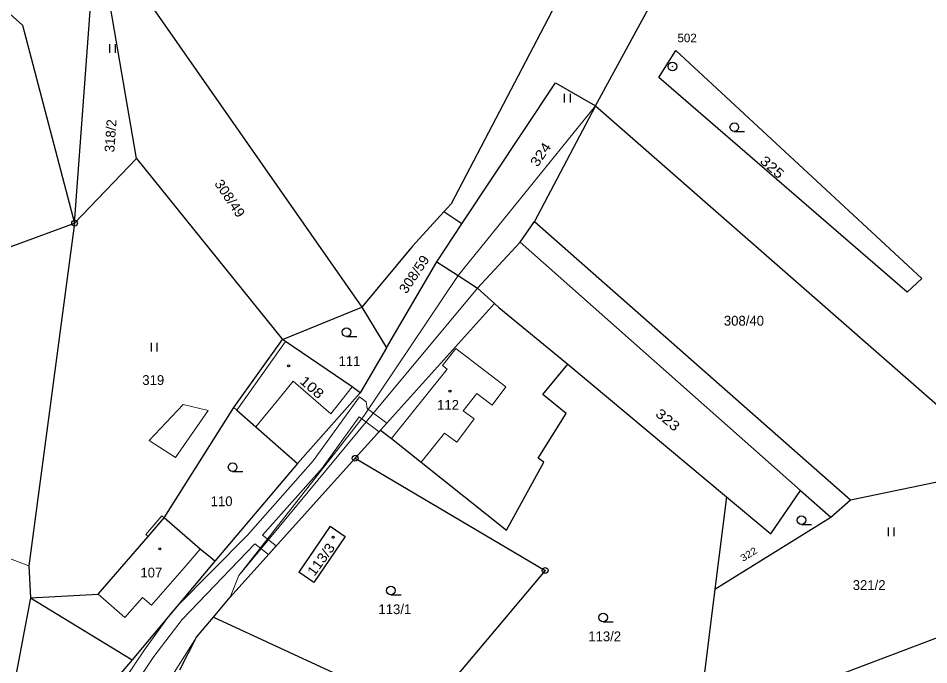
# Model space of a CAD drawing. Extents: x -504006 to -501322, y -1128098 to -1124665.
# Drawn here: x -502579.9 to -502422.2, y -1126415.1 to -1126303.1 of the extents above; entities that cross this region are included whole.
import ezdxf
from ezdxf.enums import TextEntityAlignment as Align

# ---------------------------------------------------------------- set-up
doc = ezdxf.new("R2010")
doc.units = 0
doc.header["$LTSCALE"] = 0.68
for name, color, linetype, lineweight in [('1', 7, 'Continuous', 25), ('13', 7, 'Continuous', 13), ('3', 7, 'Continuous', 25), ('4', 7, 'Continuous', 13), ('5', 7, 'Continuous', 25), ('8', 7, 'Continuous', 25)]:
    doc.layers.add(name, color=color, linetype=linetype, lineweight=lineweight)
doc.layers.add('2', color=7, linetype='Continuous')

msp = doc.modelspace()

# ---------------------------------------------------------------- linework, layer by layer
at = {"layer": '1'}
for p, q in [((-502479.92, -1126318.31), (-502455.33, -1126272.95)), ((-502479.14, -1126285.99), (-502504.93, -1126335.25)), ((-502570.14, -1126338.62), (-502566.35, -1126287.36)), ((-502566.35, -1126287.36), (-502520.38, -1126353.19)), ((-502559.39, -1126327.42), (-502566.35, -1126287.36)), ((-502595.09, -1126290.13), (-502579.17, -1126304.31)), ((-502579.17, -1126304.31), (-502570.14, -1126338.62)), ((-502468.92, -1126313.37), (-502465.98, -1126308.73)), ((-502465.98, -1126308.73), (-502423.39, -1126348.19)), ((-502425.92, -1126350.57), (-502468.92, -1126313.37)), ((-502503.06, -1126338.76), (-502486.83, -1126314.3)), ((-502486.83, -1126314.3), (-502479.92, -1126318.31)), ((-502479.92, -1126318.31), (-502490.51, -1126338.36)), ((-502479.92, -1126318.31), (-502419.28, -1126371.36)), ((-502570.14, -1126338.62), (-502559.39, -1126327.42)), ((-502559.39, -1126327.42), (-502534.14, -1126358.76)), ((-502506.21, -1126336.66), (-502504.93, -1126335.25)), ((-502506.21, -1126336.66), (-502511.61, -1126342.61)), ((-502503.06, -1126338.76), (-502506.21, -1126336.66)), ((-502595.74, -1126348), (-502570.14, -1126338.62)), ((-502570.14, -1126338.62), (-502578.06, -1126397.97)), ((-502507.41, -1126345.32), (-502503.06, -1126338.76)), ((-502492.96, -1126341.91), (-502490.51, -1126338.36)), ((-502490.51, -1126338.36), (-502435.75, -1126386.52)), ((-502500.36, -1126349.87), (-502492.96, -1126341.91)), ((-502511.61, -1126342.61), (-502520.38, -1126353.19)), ((-502516.11, -1126360.23), (-502507.41, -1126345.32)), ((-502507.41, -1126345.32), (-502503.72, -1126347.7)), ((-502503.72, -1126347.7), (-502500.36, -1126349.87)), ((-502423.39, -1126348.19), (-502425.92, -1126350.57)), ((-502500.36, -1126349.87), (-502497.4, -1126352.56)), ((-502534.14, -1126358.76), (-502520.38, -1126353.19)), ((-502520.38, -1126353.19), (-502516.11, -1126360.23)), ((-502517.13, -1126374.46), (-502497.4, -1126352.56)), ((-502497.4, -1126352.56), (-502496.69, -1126353.21)), ((-502496.69, -1126353.21), (-502484.7, -1126363.05)), ((-502542.54, -1126370.58), (-502534.14, -1126358.76)), ((-502533.61, -1126359.13), (-502534.14, -1126358.76)), ((-502522.05, -1126366.99), (-502533.61, -1126359.13)), ((-502516.11, -1126360.23), (-502520.65, -1126368)), ((-502489.03, -1126368.32), (-502484.7, -1126363.05)), ((-502484.7, -1126363.05), (-502457.2, -1126386.02)), ((-502520.65, -1126368), (-502522.05, -1126366.99)), ((-502520.65, -1126368), (-502531.53, -1126380.26)), ((-502485.01, -1126371.62), (-502489.03, -1126368.32)), ((-502554.62, -1126389.67), (-502542.54, -1126370.58)), ((-502542.54, -1126370.58), (-502542.04, -1126371.01)), ((-502542.04, -1126371.01), (-502538.73, -1126373.92)), ((-502489.82, -1126379.32), (-502485.01, -1126371.62)), ((-502538.73, -1126373.92), (-502531.53, -1126380.26)), ((-502521.54, -1126379.35), (-502517.13, -1126374.46)), ((-502517.13, -1126374.46), (-502515.28, -1126375.93)), ((-502515.28, -1126375.93), (-502510.09, -1126380.04)), ((-502488.87, -1126380.05), (-502489.82, -1126379.32)), ((-502531.53, -1126380.26), (-502545.85, -1126397.19)), ((-502510.09, -1126380.04), (-502495.32, -1126391.81)), ((-502495.32, -1126391.81), (-502488.87, -1126380.05)), ((-502435.75, -1126386.52), (-502419.38, -1126383.13)), ((-502457.2, -1126386.02), (-502459.24, -1126402.04)), ((-502457.2, -1126386.02), (-502449.53, -1126392.43)), ((-502449.53, -1126392.43), (-502444.4, -1126384.92)), ((-502444.4, -1126384.92), (-502439.16, -1126389.56)), ((-502439.16, -1126389.56), (-502435.75, -1126386.52)), ((-502557.4, -1126392.88), (-502554.62, -1126389.67)), ((-502548.38, -1126395.09), (-502554.62, -1126389.67)), ((-502459.24, -1126402.04), (-502439.16, -1126389.56)), ((-502525.88, -1126391.09), (-502531.32, -1126399.06)), ((-502525.88, -1126391.09), (-502523.28, -1126392.87)), ((-502566.08, -1126402.87), (-502557.4, -1126392.88)), ((-502523.28, -1126392.87), (-502528.72, -1126400.84)), ((-502546.6, -1126396.53), (-502548.38, -1126395.09)), ((-502545.85, -1126397.19), (-502560.18, -1126414.25)), ((-502545.85, -1126397.19), (-502546.6, -1126396.53)), ((-502578.06, -1126397.97), (-502577.79, -1126403.55)), ((-502488.63, -1126398.78), (-502517.33, -1126432.89)), ((-502528.72, -1126400.84), (-502531.32, -1126399.06)), ((-502459.24, -1126402.04), (-502462.2, -1126425.6)), ((-502577.79, -1126403.55), (-502581.3, -1126422.25)), ((-502577.79, -1126403.55), (-502566.08, -1126402.87)), ((-502577.79, -1126403.55), (-502560.18, -1126414.25)), ((-502546.11, -1126406.89), (-502543.22, -1126403.41)), ((-502446.8, -1126420.25), (-502404.96, -1126404.48)), ((-502549, -1126410.36), (-502546.11, -1126406.89)), ((-502546.11, -1126406.89), (-502523.76, -1126417.19)), ((-502551.92, -1126415.99), (-502549, -1126410.36)), ((-502560.18, -1126414.25), (-502562.43, -1126416.93))]:
    msp.add_line(p, q, dxfattribs=at)
msp.add_lwpolyline([(-502543.22, -1126403.41), (-502521.54, -1126379.35), (-502488.63, -1126398.78)], dxfattribs=at)
at = {"layer": '13'}
msp.add_lwpolyline([(-502561.33, -1126421.06), (-502556.4, -1126413.68), (-502551.52, -1126407.26), (-502538.92, -1126394.17), (-502536.57, -1126396.03), (-502535.23, -1126394.54), (-502537.58, -1126392.68), (-502527.24, -1126381.06), (-502520.84, -1126372.18), (-502517.4, -1126374.76), (-502517.13, -1126374.46), (-502516.06, -1126373.27), (-502519.49, -1126370.7), (-502519.66, -1126369.57), (-502520.82, -1126368.72), (-502528.8, -1126379.8), (-502540.22, -1126392.64), (-502552.42, -1126405.01), (-502553.72, -1126406.55), (-502558.02, -1126412.52), (-502563.03, -1126420)], dxfattribs=at)
at = {"layer": '3'}
for p, q in [((-502564.061, -1126309.1), (-502564.061, -1126307.6)), ((-502563.06, -1126309.1), (-502563.06, -1126307.6)), ((-502485.261, -1126317.71), (-502485.261, -1126316.21)), ((-502484.26, -1126317.71), (-502484.26, -1126316.21)), ((-502455.873, -1126322.74), (-502454.123, -1126322.74)), ((-502556.831, -1126360.83), (-502556.831, -1126359.33)), ((-502555.83, -1126360.83), (-502555.83, -1126359.33)), ((-502523.033, -1126358.28), (-502521.283, -1126358.28)), ((-502542.763, -1126381.65), (-502541.013, -1126381.65)), ((-502444.243, -1126390.82), (-502442.493, -1126390.82)), ((-502429.171, -1126392.85), (-502429.171, -1126391.35)), ((-502428.17, -1126392.85), (-502428.17, -1126391.35)), ((-502515.353, -1126403), (-502513.603, -1126403)), ((-502478.583, -1126407.69), (-502476.833, -1126407.69))]:
    msp.add_line(p, q, dxfattribs=at)
for centre in [(-502455.8729, -1126321.9898), (-502523.0329, -1126357.5298), (-502542.7629, -1126380.8998), (-502444.2429, -1126390.0698), (-502515.3529, -1126402.2498), (-502478.5829, -1126406.9398)]:
    msp.add_circle(centre, 0.75, dxfattribs=at)
at = {"layer": '4'}
for p, q in [((-502479.92, -1126318.31), (-502503.72, -1126347.7)), ((-502492.96, -1126341.91), (-502444.4, -1126384.92)), ((-502503.72, -1126347.7), (-502520.13, -1126372.09)), ((-502519.34, -1126372.71), (-502500.36, -1126349.87)), ((-502542.04, -1126371.01), (-502533.61, -1126359.13)), ((-502506.4, -1126363.29), (-502504.12, -1126360.35)), ((-502504.12, -1126360.35), (-502495.44, -1126366.97)), ((-502515.28, -1126375.93), (-502505.59, -1126363.89)), ((-502505.59, -1126363.89), (-502506.4, -1126363.29)), ((-502532.3, -1126366.01), (-502534.5, -1126368.71)), ((-502525.76, -1126371.67), (-502532.3, -1126366.01)), ((-502522.05, -1126366.99), (-502525.76, -1126371.67)), ((-502495.44, -1126366.97), (-502497.81, -1126370.13)), ((-502534.5, -1126368.71), (-502538.73, -1126373.92)), ((-502500.45, -1126368.12), (-502502.83, -1126371.12)), ((-502497.81, -1126370.13), (-502500.45, -1126368.12)), ((-502557.25, -1126376.27), (-502551.32, -1126370.01)), ((-502551.32, -1126370.01), (-502547.01, -1126371.1)), ((-502547.01, -1126371.1), (-502552.66, -1126379.23)), ((-502520.13, -1126372.09), (-502541.71, -1126399.64)), ((-502502.83, -1126371.12), (-502500.94, -1126372.49)), ((-502541.71, -1126399.64), (-502519.34, -1126372.71)), ((-502500.94, -1126372.49), (-502503.95, -1126376.57)), ((-502506.07, -1126375.01), (-502510.09, -1126380.04)), ((-502503.95, -1126376.57), (-502506.07, -1126375.01)), ((-502552.66, -1126379.23), (-502557.25, -1126376.27)), ((-502555.02, -1126389.32), (-502557.8, -1126392.53)), ((-502554.62, -1126389.67), (-502555.02, -1126389.32)), ((-502557.8, -1126392.53), (-502557.4, -1126392.88)), ((-502578.06, -1126397.97), (-502588.48, -1126394.04)), ((-502548.38, -1126395.09), (-502551.19, -1126398.31)), ((-502551.19, -1126398.31), (-502556.82, -1126404.81)), ((-502543.22, -1126403.41), (-502541.71, -1126399.64)), ((-502561.42, -1126406.92), (-502566.08, -1126402.87)), ((-502558.4, -1126403.44), (-502561.42, -1126406.92)), ((-502556.82, -1126404.81), (-502558.4, -1126403.44)), ((-502549, -1126410.36), (-502568.73, -1126441.07))]:
    msp.add_line(p, q, dxfattribs=at)
at = {"layer": '5'}
for centre in [(-502533.0668, -1126363.3192), (-502505.1268, -1126367.7392), (-502525.3668, -1126393.0392), (-502555.3668, -1126395.0492)]:
    msp.add_circle(centre, 0.175, dxfattribs=at)
at = {"layer": '8'}
for centre, radius in [((-502466.6, -1126311.4898), 0.75), ((-502466.6, -1126311.4898), 0.03), ((-502570.14, -1126338.6199), 0.5), ((-502570.14, -1126338.6199), 0.0303), ((-502521.54, -1126379.3499), 0.5), ((-502521.54, -1126379.3499), 0.0303), ((-502488.63, -1126398.7799), 0.5), ((-502488.63, -1126398.7799), 0.0303)]:
    msp.add_circle(centre, radius, dxfattribs=at)

# ---------------------------------------------------------------- texts
at = {"layer": '2'}
msp.add_text('318/2', height=1.7, rotation=86, dxfattribs=at).set_placement((-502563.073, -1126323.5583), align=Align.CENTER)
for s, height, rotation, width, p in [('324', 1.7, 56, 1.15, (-502488.7344, -1126327.2153)), ('325', 1.7, 319, 1.2, (-502449.8741, -1126329.5672)), ('308/49', 1.7, 304, 1.05, (-502543.9584, -1126334.7987)), ('308/59', 1.7, 56, 1.05, (-502510.6344, -1126347.9553)), ('108', 1.7, 319, 1.2, (-502529.5841, -1126367.6872)), ('323', 1.7, 320, 1.2, (-502467.9444, -1126373.3388)), ('322', 1.2, 32, 1.15, (-502453.068, -1126396.4824))]:
    msp.add_text(s, height=height, rotation=rotation, dxfattribs=dict(at, width=width)).set_placement(p, align=Align.CENTER)
for s, p in [('308/40', (-502454.21, -1126356.375)), ('111', (-502522.529, -1126363.375)), ('319', (-502556.519, -1126366.655)), ('112', (-502505.459, -1126370.955)), ('110', (-502544.679, -1126387.645)), ('107', (-502556.849, -1126399.995)), ('321/2', (-502432.52, -1126402.165)), ('113/1', (-502514.67, -1126406.345)), ('113/2', (-502478.33, -1126411.045))]:
    msp.add_text(s, height=1.7, dxfattribs=at).set_placement(p, align=Align.CENTER)
at = {"layer": '2', "width": 1.1}
msp.add_text('113/3', height=1.7, rotation=54, dxfattribs=at).set_placement((-502528.616, -1126399.899))
at = {"layer": '8'}
msp.add_text('502', height=1.5, dxfattribs=at).set_placement((-502462.379, -1126307.295), align=Align.RIGHT)

doc.saveas('drawing.dxf')
